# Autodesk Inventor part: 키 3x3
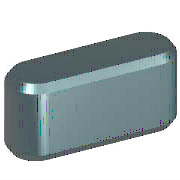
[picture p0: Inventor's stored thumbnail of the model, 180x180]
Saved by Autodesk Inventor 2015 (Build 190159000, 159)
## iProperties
Created: 2012-02
Part Number: 키 3x3
Material: 강철, 연강
Description: 키 및 해당 키홈
Document SubType Name: Modeling
Standard: KS B 1311
Designer: mduedu
Standards Organization: KS
Language: ko-KR
Size Designation: 3 x 3 x 12
Categories: <MemberInstance><Categories><Category DisplayName="샤프트 부품" InternalName="7f7aeb1f-a693-4053-b835-cee3144e0d98" Mnemonic="SHFT"><Category DisplayName="키" Interna
Density: 1 g/cm^3
Appearance: 노란색
IsCustomPart: 1
Author: mduedu
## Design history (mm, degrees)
workplane "Work Plane1"
workplane "Work Plane2"
sketch "스케치1"
  geometry: L1 (1.5, 1.5)-(10.5, 1.5); L2 (10.5, -1.5)-(1.5, -1.5); L3 (0, 9.4)-(0, -7.4) reference; L4 (-5, 0)-(30, 0) reference; L5 (12, 0)-(12, 7); A1 r 1.5 centre (1.5, 0) between (1.5, 1.5) and (1.5, -1.5); A2 r 1.5 centre (10.5, 0) between (10.5, -1.5) and (10.5, 1.5)
  constraints: 6 end point, 5 point on circle, 4 tangent, 3 point on line, 2 centre point, 1 horizontal, 1 parallel, 1 perpendicular
  dimensions: "d0" = 1.5 radius of A1 (= 0.5 x PB); "d13" = 1.5 radius of A2 (= 0.5 x PB); "d14" = 12 distance between parallel lines of L5 L3 (= NLG)
extrude "본체1" new body sketch "스케치1" taper "d3" = 0 deg; stored distance "d4" = 10
workplane "Work Plane3"
body "Solid1"
chamfer "모따기1" distance "d8" = 0.25 (= PHH); stored, may be unused: second distance "d9" = 0.25 (= PHH), angle "d15" = 45 deg
other parameters: "d1" = -1.8 (= -PNT), "d2" = 1.2 (= PH - PNT), "NLG" = 12 [user parameter; used in 3 equation terms], "PB" = 3 [user parameter; used in 2 equation terms], "PNT" = 1.8 [user parameter; used in 2 equation terms], "PH" = 3 [user parameter; used in 1 equation term], "PHH" = 0.25 [user parameter; used in 2 equation terms], "d10" = 0, "d16" = 0, "d17" = 0, "d18" = 0, "WDMIN" = 8 [user parameter], "PLB2" = 12 (= NLG) [user parameter], "PLB1" = 12 (= NLG) [user parameter], "RR" = 0.08 [user parameter], "PUEB" = 1.4 [user parameter]
